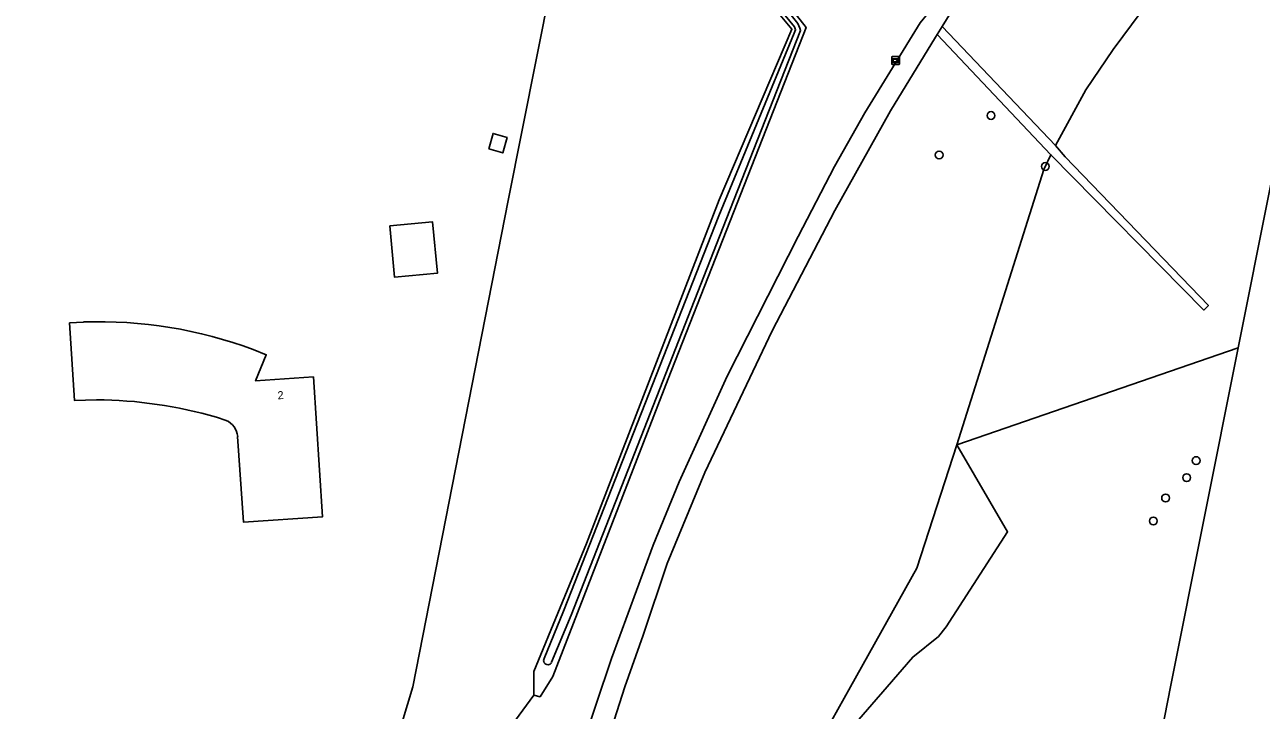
# Model space of a CAD drawing. Extents: x 162417 to 163722, y 384268 to 385417.
# Drawn here: x 162964 to 163118.6, y 385247.1 to 385332.8 of the extents above; entities that cross this region are included whole.
import ezdxf

# ---------------------------------------------------------------- set-up
doc = ezdxf.new("R2010")
doc.units = 0
for name, color, linetype in [('IMGEO_Boom', 7, 'Continuous'), ('IMGEO_Erf', 7, 'Continuous'), ('IMGEO_Gemengd_bos', 7, 'Continuous'), ('IMGEO_Groenvoorziening', 7, 'Continuous'), ('IMGEO_Oever', 7, 'Continuous'), ('IMGEO_Pand', 7, 'Continuous'), ('IMGEO_Pand_nummerreeks', 7, 'Continuous'), ('IMGEO_Voetpad_halfverhard', 7, 'Continuous'), ('IMGEO_Waterloop', 7, 'Continuous'), ('IMGEO_Wegwijzer', 7, 'Continuous')]:
    doc.layers.add(name, color=color, linetype=linetype)

msp = doc.modelspace()

# ---------------------------------------------------------------- linework, layer by layer
at = {"layer": 'IMGEO_Boom'}
for centre in [(163084.79, 385321.44), (163078.31, 385316.51), (163091.58, 385315.07), (163110.43, 385278.28), (163109.25, 385276.15), (163106.61, 385273.61), (163105.08, 385270.73)]:
    msp.add_circle(centre, 0.489, dxfattribs=at)
at = {"layer": 'IMGEO_Erf'}
for points in [[(162977.02, 385225.24), (162980.92, 385219.88), (162983.1, 385215.85), (162999.67, 385223.85), (163002.31, 385228.02), (163005.52, 385233.58), (163009.66, 385241.99), (163011.19, 385245.56), (163012.52, 385250), (163024.43, 385310.81), (163029.79, 385337.67), (162986.75, 385346.16), (162983.96, 385346.72), (162964.03, 385350.65)], [(163123.47, 385331.45), (163115.67, 385292.37), (163107.22, 385250), (163103.3, 385229.91), (163087.26, 385230.97), (163087.35, 385230.19), (163089.09, 385214.58), (163090.71, 385200.08), (163093.74, 385172.91), (163098.45, 385137), (163098.96, 385135.24), (163080.24, 385131.33), (163083.11, 385123.51), (163095.42, 385082.81), (163109.64, 385035.76), (163200.68, 385063.02)], [(162973, 385285.9), (162970.26, 385285.79), (162969.63, 385295.5), (162971.38, 385295.61)], [(162992.58, 385292.16), (162994.21, 385291.52), (162992.87, 385288.25), (163000.1, 385288.75)], [(163000.1, 385288.75), (163001.24, 385271.23), (162991.35, 385270.58), (162990.64, 385281.29)], [(162989.2, 385283.3), (162987.98, 385283.71)]]:
    msp.add_lwpolyline(points, dxfattribs=at)
for points in [[(163022.02, 385317.27), (163022.57, 385319.2), (163024.32, 385318.71), (163023.77, 385316.77)], [(163009.64, 385307.63), (163014.99, 385308.14), (163015.61, 385301.72), (163010.25, 385301.21)]]:
    msp.add_lwpolyline(points, close=True, dxfattribs=at)
for centre, radius, start, end in [((162973.31, 385240.62), 55.03, 69.4939, 92.0102), ((162972.48, 385229.92), 55.98, 73.9298, 89.464), ((162988.23, 385281.09), 2.42, 4.7975, 66.3693)]:
    msp.add_arc(centre, radius, start, end, dxfattribs=at)
at = {"layer": 'IMGEO_Gemengd_bos'}
msp.add_lwpolyline([(163134.87, 385346.57), (163129.12, 385354.44), (163103.55, 385334.4), (163100.06, 385329.69), (163096.66, 385324.65), (163092.84, 385317.68), (163094.06, 385316.26), (163111.97, 385297.66), (163111.38, 385297.11), (163092.28, 385316.53), (163091.39, 385314.7), (163080.54, 385280.24), (163115.67, 385292.37), (163123.47, 385331.45), (163125.26, 385340.42), (163154.66, 385322.14), (163171.61, 385317.19), (163171.93, 385318.81), (163149.97, 385333.18)], dxfattribs=at)
for points in [[(163107.22, 385250), (163115.67, 385292.37), (163080.54, 385280.24), (163086.86, 385269.38), (163079.19, 385257.47), (163078.22, 385256.3), (163075.02, 385253.7), (163071.81, 385250), (163060.59, 385237.05), (163057.27, 385229.43), (163054.51, 385220.49), (163053.47, 385216.03), (163053.02, 385211.75), (163056.37, 385211.01), (163056.72, 385199.79), (163090.71, 385200.08), (163089.09, 385214.58), (163087.35, 385230.19), (163087.26, 385230.97), (163103.3, 385229.91)], [(163071.81, 385250), (163075.02, 385253.7), (163078.22, 385256.3), (163079.19, 385257.47), (163086.86, 385269.38), (163080.54, 385280.24), (163075.52, 385264.83), (163067.23, 385250), (163064.85, 385245.75), (163062.04, 385240.39), (163060.59, 385237.05)]]:
    msp.add_lwpolyline(points, close=True, dxfattribs=at)
at = {"layer": 'IMGEO_Groenvoorziening'}
for points in [[(163122.71, 385369.45), (163120.56, 385378.46), (163108.97, 385366), (163097.9, 385353.97), (163087.24, 385342.4), (163079.77, 385334.32), (163078.68, 385332.56), (163092.84, 385317.68), (163096.66, 385324.65), (163100.06, 385329.69), (163103.55, 385334.4), (163129.12, 385354.44)], [(162967.17, 385354.52), (162964.03, 385350.65), (162983.96, 385346.72), (162986.75, 385346.16), (163029.79, 385337.67), (163024.43, 385310.81), (163012.52, 385250), (163011.19, 385245.56)], [(163047.67, 385350.42), (163061.68, 385332.47), (163044.45, 385288.5), (163030.01, 385251.27), (163028.43, 385248.75), (163027.67, 385248.94), (163019.63, 385237.96), (162993.26, 385185.69), (162995.25, 385176.49), (162997.06, 385163.99), (162998.03, 385154.51), (162998.95, 385150.01), (163000, 385142.56), (163002.25, 385125.39), (163004.52, 385111.54), (163004.66, 385109.53), (163006.03, 385098.33), (163007.34, 385084.81), (163008.65, 385073.79), (163009.84, 385060.55), (163010.41, 385056.14), (163012.68, 385031.16), (163013.78, 385015.41)], [(163019.63, 385237.96), (163027.67, 385248.94), (163027.67, 385251.91), (163034.23, 385267.93), (163050.83, 385310.9), (163059.91, 385332.22), (163046.16, 385348.81)], [(163033.48, 385241.98), (163037.34, 385253.52), (163042.57, 385267.72), (163045.81, 385275.63), (163051.83, 385288.85), (163060.69, 385306.29), (163065.22, 385315.05), (163069.02, 385321.76), (163075.92, 385333.04)], [(163064.85, 385245.75), (163067.23, 385250), (163075.52, 385264.83), (163080.54, 385280.24), (163091.39, 385314.7), (163092.28, 385316.53), (163078.07, 385331.58), (163077.87, 385331.26), (163072.21, 385322.02), (163065.28, 385309.54), (163057.46, 385294.51), (163049.04, 385276.79), (163044.33, 385265.41), (163041.33, 385256.44), (163039.04, 385250), (163034.13, 385234.62)]]:
    msp.add_lwpolyline(points, dxfattribs=at)
at = {"layer": 'IMGEO_Oever'}
for points in [[(162969.15, 385356.88), (162969.63, 385357.25), (162982.42, 385366.21), (162984.69, 385367.47), (162987.51, 385368.27), (162989.54, 385368.52), (162991.49, 385368.65), (162993.52, 385368.6), (162995.24, 385368.18), (163032.28, 385358.41), (163036, 385357.33), (163038.6, 385356.27), (163041.71, 385354.62), (163043.86, 385353.13), (163045.92, 385351.53), (163047.28, 385349.92), (163048.35, 385348.37), (163060.66, 385332.94), (163060.9, 385332.37), (163060.99, 385332.06), (163051.71, 385308.42), (163032.31, 385258.96), (163029.88, 385253.05)], [(163044.45, 385288.5), (163061.68, 385332.47), (163047.67, 385350.42)], [(163046.16, 385348.81), (163059.91, 385332.22), (163050.83, 385310.9), (163034.23, 385267.93), (163027.67, 385251.91), (163027.67, 385248.94), (163028.43, 385248.75), (163030.01, 385251.27), (163044.45, 385288.5)], [(163028.95, 385253.54), (163031.38, 385259.46), (163050.78, 385308.91), (163060.2, 385331.75), (163060.36, 385332.16), (163060.22, 385332.54), (163047.07, 385348.57)]]:
    msp.add_lwpolyline(points, dxfattribs=at)
msp.add_arc((163029.41, 385253.28), 0.527, 150.0028, 333.801, dxfattribs=at)
at = {"layer": 'IMGEO_Pand'}
for points in [[(163022.02, 385317.27), (163023.77, 385316.77), (163024.32, 385318.71), (163022.57, 385319.2)], [(163009.64, 385307.63), (163010.25, 385301.21), (163015.61, 385301.72), (163014.99, 385308.14)]]:
    msp.add_lwpolyline(points, close=True, dxfattribs=at)
for points in [[(162971.38, 385295.61), (162969.63, 385295.5), (162970.26, 385285.79), (162973, 385285.9)], [(163000.1, 385288.75), (162992.87, 385288.25), (162994.21, 385291.52), (162992.58, 385292.16)], [(162990.64, 385281.29), (162991.35, 385270.58), (163001.24, 385271.23), (163000.1, 385288.75)], [(162987.98, 385283.71), (162989.2, 385283.3)]]:
    msp.add_lwpolyline(points, dxfattribs=at)
for centre, radius, start, end in [((162973.31, 385240.62), 55.03, 69.4939, 92.0102), ((162972.48, 385229.92), 55.98, 73.9298, 89.464), ((162988.23, 385281.09), 2.42, 4.7975, 66.3693)]:
    msp.add_arc(centre, radius, start, end, dxfattribs=at)
at = {"layer": 'IMGEO_Voetpad_halfverhard'}
for points in [[(163121.67, 385383.32), (163109.06, 385369.37), (163095.28, 385354.73), (163079.76, 385337.73), (163075.92, 385333.04), (163069.02, 385321.76), (163065.22, 385315.05), (163060.69, 385306.29), (163051.83, 385288.85), (163045.81, 385275.63), (163042.57, 385267.72), (163037.34, 385253.52), (163033.48, 385241.98), (163031.15, 385233.91), (163030.02, 385230.17), (163026.09, 385216.88), (163024.11, 385208.78), (163023.12, 385204.29), (163021.14, 385194.9), (163018.46, 385178.56), (163016.83, 385164.9), (163015.77, 385153.98)], [(163034.13, 385234.62), (163039.04, 385250), (163041.33, 385256.44), (163044.33, 385265.41), (163049.04, 385276.79), (163057.46, 385294.51), (163065.28, 385309.54), (163072.21, 385322.02), (163077.87, 385331.26), (163078.07, 385331.58), (163078.68, 385332.56), (163079.77, 385334.32), (163087.24, 385342.4), (163097.9, 385353.97), (163108.97, 385366), (163120.56, 385378.46)]]:
    msp.add_lwpolyline(points, dxfattribs=at)
at = {"layer": 'IMGEO_Waterloop'}
for points in [[(163029.88, 385253.05), (163032.31, 385258.96), (163051.71, 385308.42), (163060.99, 385332.06), (163060.9, 385332.37), (163060.66, 385332.94), (163048.35, 385348.37), (163047.28, 385349.92), (163045.92, 385351.53), (163043.86, 385353.13), (163041.71, 385354.62), (163038.6, 385356.27), (163036, 385357.33), (163032.28, 385358.41), (162995.24, 385368.18), (162993.52, 385368.6), (162991.49, 385368.65), (162989.54, 385368.52), (162987.51, 385368.27), (162984.69, 385367.47), (162982.42, 385366.21), (162969.63, 385357.25)], [(163047.07, 385348.57), (163060.22, 385332.54), (163060.36, 385332.16), (163060.2, 385331.75), (163050.78, 385308.91), (163031.38, 385259.46), (163028.95, 385253.54)]]:
    msp.add_lwpolyline(points, dxfattribs=at)
msp.add_lwpolyline([(163094.06, 385316.26), (163092.84, 385317.68), (163078.68, 385332.56), (163078.07, 385331.58), (163092.28, 385316.53), (163111.38, 385297.11), (163111.97, 385297.66)], close=True, dxfattribs=at)
msp.add_arc((163029.41, 385253.28), 0.527, 150.0028, 333.801, dxfattribs=at)
at = {"layer": 'IMGEO_Wegwijzer'}
for p, q in [((163072.38, 385327.92), (163072.38, 385328.71)), ((163072.38, 385328.71), (163072.38, 385327.92)), ((163072.48, 385328.81), (163073.27, 385328.81)), ((163073.27, 385328.81), (163072.48, 385328.81)), ((163073.27, 385327.82), (163072.48, 385327.82)), ((163072.48, 385327.82), (163073.27, 385327.82)), ((163073.37, 385328.71), (163073.37, 385327.92)), ((163073.37, 385327.92), (163073.37, 385328.71))]:
    msp.add_line(p, q, dxfattribs=at)
for points in [[(163072.48, 385328.55), (163073.27, 385328.55), (163073.27, 385328.08), (163072.48, 385328.08), (163072.48, 385328.55)], [(163072.55, 385328.48), (163072.55, 385328.15), (163073.21, 385328.15), (163073.21, 385328.48), (163072.55, 385328.48)]]:
    msp.add_lwpolyline(points, dxfattribs=at)
for centre, start, end in [((163072.48, 385328.71), 90, 180), ((163072.48, 385328.71), 90, 180), ((163072.48, 385327.92), 180, 270), ((163072.48, 385327.92), 180, 270), ((163073.27, 385328.71), 0, 90), ((163073.27, 385328.71), 360, 90), ((163073.27, 385327.92), 270, 0), ((163073.27, 385327.92), 270, 0)]:
    msp.add_arc(centre, 0.1, start, end, dxfattribs=at)

# ---------------------------------------------------------------- texts
at = {"layer": 'IMGEO_Pand_nummerreeks'}
msp.add_text('2', height=1, rotation=3.7185, dxfattribs=at).set_placement((162995.66, 385285.94))

doc.saveas('drawing.dxf')
